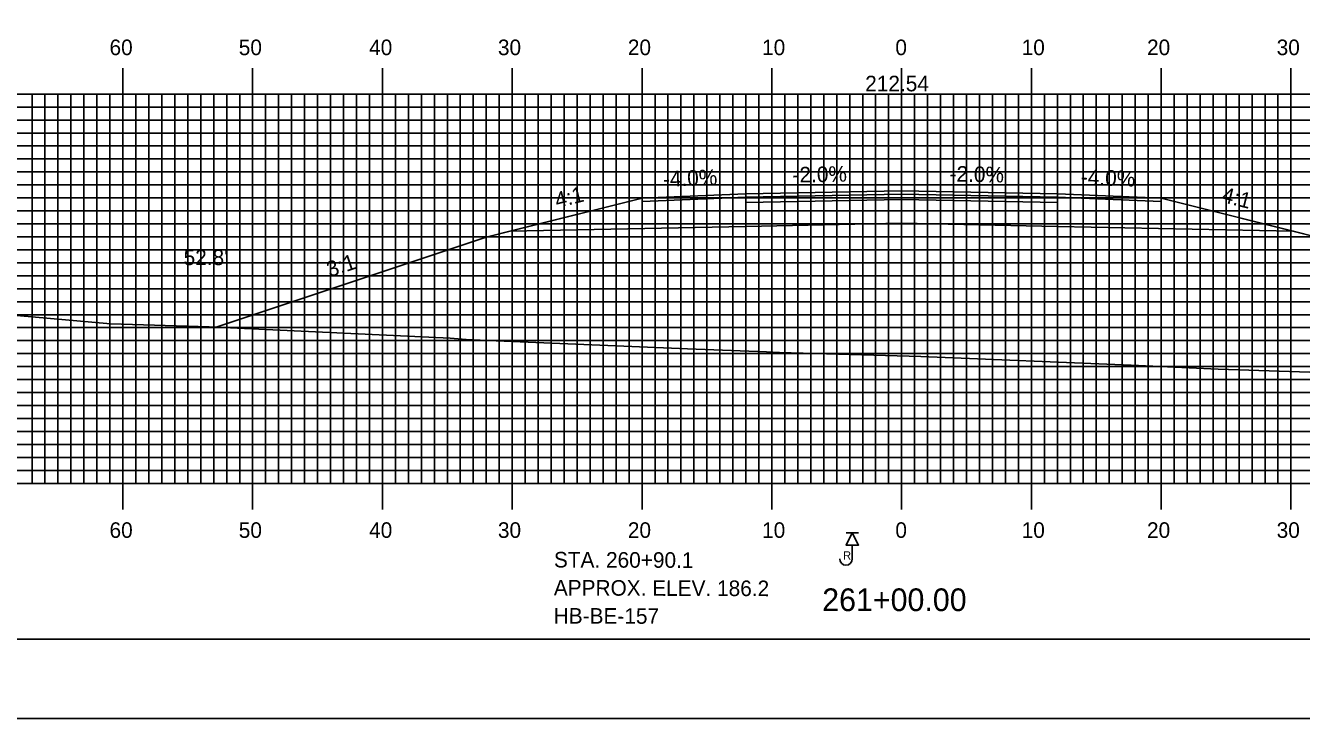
# Model space of a CAD drawing. Extents: x 1806258 to 1806601, y 442591 to 442811.
# Drawn here: x 1806356.2 to 1806454.5, y 442590.5 to 442643.9 of the extents above; entities that cross this region are included whole.
import ezdxf

# ---------------------------------------------------------------- set-up
doc = ezdxf.new("R2010")
doc.units = 0
for name, color, linetype in [('ANNOTATION', 7, 'Continuous'), ('BORDER', 7, 'Continuous'), ('BORING - REFUSAL', 7, 'Continuous'), ('D_Roadway_Centerline', 7, 'Continuous'), ('D_Roadway_Centerline_Text', 7, 'Continuous'), ('D_Roadway_Edge_Shoulder', 7, 'Continuous'), ('D_Roadway_Edge_TW', 7, 'Continuous'), ('D_Roadway_Pavement', 7, 'Continuous'), ('D_Roadway_SlopeLines', 7, 'Continuous'), ('D_Roadway_SubGrade', 7, 'Continuous'), ('D_Text_Standard', 7, 'Continuous'), ('H_V ANNOTATION', 7, 'Continuous'), ('MAJOR', 7, 'Continuous'), ('MINOR', 7, 'Continuous'), ('PLOT BOUNDARY', 7, 'Continuous'), ('S_Roadway_Centerline', 7, 'Continuous')]:
    doc.layers.add(name, color=color, linetype=linetype)

msp = doc.modelspace()

# ---------------------------------------------------------------- linework, layer by layer
at = {"layer": 'BORDER'}
msp.add_lwpolyline([(1806274.133, 442596.665), (1806594.133, 442596.665), (1806594.133, 442806.665), (1806274.133, 442806.665)], close=True, dxfattribs=at)
at = {"layer": 'BORING - REFUSAL'}
for p, q in [((1806420.412, 442604.865), (1806419.453, 442604.865)), ((1806419.933, 442603.906), (1806419.933, 442602.847))]:
    msp.add_line(p, q, dxfattribs=at)
msp.add_lwpolyline([(1806419.933, 442604.865), (1806420.412, 442603.906), (1806419.453, 442603.906)], close=True, dxfattribs=at)
msp.add_arc((1806419.448, 442602.847), 0.485, 180, 0, dxfattribs=at)
at = {"layer": 'D_Roadway_Centerline'}
msp.add_lwpolyline([(1806370.932, 442620.713), (1806391.733, 442627.646), (1806393.559, 442628.103), (1806403.733, 442630.646), (1806411.733, 442630.966), (1806423.733, 442631.206), (1806435.733, 442630.966), (1806443.733, 442630.646), (1806453.907, 442628.103), (1806455.733, 442627.646), (1806490.643, 442616.01)], dxfattribs=at)
at = {"layer": 'D_Roadway_Edge_Shoulder'}
for points in [[(1806411.733, 442630.966), (1806403.733, 442630.646), (1806403.733, 442630.396), (1806411.733, 442630.716)], [(1806435.733, 442630.966), (1806443.733, 442630.646), (1806443.733, 442630.396), (1806435.733, 442630.716)]]:
    msp.add_lwpolyline(points, close=True, dxfattribs=at)
at = {"layer": 'D_Roadway_Edge_TW'}
msp.add_lwpolyline([(1806411.733, 442630.716), (1806411.733, 442630.966), (1806423.733, 442631.206), (1806435.733, 442630.966), (1806435.733, 442630.716), (1806423.733, 442630.956)], close=True, dxfattribs=at)
at = {"layer": 'D_Roadway_Pavement'}
msp.add_lwpolyline([(1806411.733, 442630.3), (1806411.733, 442630.716), (1806423.733, 442630.956), (1806435.733, 442630.716), (1806435.733, 442630.3), (1806423.733, 442630.54)], close=True, dxfattribs=at)
at = {"layer": 'D_Roadway_SlopeLines'}
for points in [[(1806403.733, 442630.646), (1806391.733, 442627.646), (1806370.932, 442620.713)], [(1806443.733, 442630.646), (1806455.733, 442627.646), (1806490.643, 442616.01)]]:
    msp.add_lwpolyline(points, dxfattribs=at)
at = {"layer": 'D_Roadway_SubGrade'}
msp.add_lwpolyline([(1806411.733, 442628.466), (1806393.559, 442628.103), (1806403.733, 442630.646), (1806403.733, 442630.396), (1806411.733, 442630.716), (1806423.733, 442630.956), (1806435.733, 442630.716), (1806443.733, 442630.396), (1806443.733, 442630.646), (1806453.907, 442628.103), (1806435.733, 442628.466), (1806423.733, 442628.706)], close=True, dxfattribs=at)
at = {"layer": 'MAJOR'}
for p, q in [((1806363.733, 442640.669), (1806363.733, 442638.665)), ((1806373.733, 442640.669), (1806373.733, 442638.665)), ((1806383.733, 442640.669), (1806383.733, 442638.665)), ((1806393.733, 442640.669), (1806393.733, 442638.665)), ((1806403.733, 442640.669), (1806403.733, 442638.665)), ((1806413.733, 442640.669), (1806413.733, 442638.665)), ((1806423.733, 442640.669), (1806423.733, 442638.665)), ((1806433.733, 442640.669), (1806433.733, 442638.665)), ((1806443.733, 442640.669), (1806443.733, 442638.665)), ((1806453.733, 442640.669), (1806453.733, 442638.665)), ((1806283.733, 442638.665), (1806563.733, 442638.665)), ((1806283.733, 442638.665), (1806563.733, 442638.665)), ((1806363.733, 442608.665), (1806363.733, 442638.665)), ((1806373.733, 442608.665), (1806373.733, 442638.665)), ((1806383.733, 442608.665), (1806383.733, 442638.665)), ((1806393.733, 442608.665), (1806393.733, 442638.665)), ((1806403.733, 442608.665), (1806403.733, 442638.665)), ((1806413.733, 442608.665), (1806413.733, 442638.665)), ((1806423.733, 442608.665), (1806423.733, 442638.665)), ((1806433.733, 442608.665), (1806433.733, 442638.665)), ((1806443.733, 442608.665), (1806443.733, 442638.665)), ((1806453.733, 442608.665), (1806453.733, 442638.665)), ((1806283.733, 442633.665), (1806563.733, 442633.665)), ((1806283.733, 442628.665), (1806563.733, 442628.665)), ((1806283.733, 442623.665), (1806563.733, 442623.665)), ((1806283.733, 442618.665), (1806563.733, 442618.665)), ((1806283.733, 442613.665), (1806563.733, 442613.665)), ((1806283.733, 442608.665), (1806563.733, 442608.665)), ((1806283.733, 442608.665), (1806563.733, 442608.665)), ((1806363.733, 442606.661), (1806363.733, 442608.665)), ((1806373.733, 442606.661), (1806373.733, 442608.665)), ((1806383.733, 442606.661), (1806383.733, 442608.665)), ((1806393.733, 442606.661), (1806393.733, 442608.665)), ((1806403.733, 442606.661), (1806403.733, 442608.665)), ((1806413.733, 442606.661), (1806413.733, 442608.665)), ((1806423.733, 442606.661), (1806423.733, 442608.665)), ((1806433.733, 442606.661), (1806433.733, 442608.665)), ((1806443.733, 442606.661), (1806443.733, 442608.665)), ((1806453.733, 442606.661), (1806453.733, 442608.665))]:
    msp.add_line(p, q, dxfattribs=at)
at = {"layer": 'MINOR'}
for p, q in [((1806356.733, 442608.665), (1806356.733, 442638.665)), ((1806357.733, 442608.665), (1806357.733, 442638.665)), ((1806358.733, 442608.665), (1806358.733, 442638.665)), ((1806359.733, 442608.665), (1806359.733, 442638.665)), ((1806360.733, 442608.665), (1806360.733, 442638.665)), ((1806361.733, 442608.665), (1806361.733, 442638.665)), ((1806362.733, 442608.665), (1806362.733, 442638.665)), ((1806364.733, 442608.665), (1806364.733, 442638.665)), ((1806365.733, 442608.665), (1806365.733, 442638.665)), ((1806366.733, 442608.665), (1806366.733, 442638.665)), ((1806367.733, 442608.665), (1806367.733, 442638.665)), ((1806368.733, 442608.665), (1806368.733, 442638.665)), ((1806369.733, 442608.665), (1806369.733, 442638.665)), ((1806370.733, 442608.665), (1806370.733, 442638.665)), ((1806371.733, 442608.665), (1806371.733, 442638.665)), ((1806372.733, 442608.665), (1806372.733, 442638.665)), ((1806374.733, 442608.665), (1806374.733, 442638.665)), ((1806375.733, 442608.665), (1806375.733, 442638.665)), ((1806376.733, 442608.665), (1806376.733, 442638.665)), ((1806377.733, 442608.665), (1806377.733, 442638.665)), ((1806378.733, 442608.665), (1806378.733, 442638.665)), ((1806379.733, 442608.665), (1806379.733, 442638.665)), ((1806380.733, 442608.665), (1806380.733, 442638.665)), ((1806381.733, 442608.665), (1806381.733, 442638.665)), ((1806382.733, 442608.665), (1806382.733, 442638.665)), ((1806384.733, 442608.665), (1806384.733, 442638.665)), ((1806385.733, 442608.665), (1806385.733, 442638.665)), ((1806386.733, 442608.665), (1806386.733, 442638.665)), ((1806387.733, 442608.665), (1806387.733, 442638.665)), ((1806388.733, 442608.665), (1806388.733, 442638.665)), ((1806389.733, 442608.665), (1806389.733, 442638.665)), ((1806390.733, 442608.665), (1806390.733, 442638.665)), ((1806391.733, 442608.665), (1806391.733, 442638.665)), ((1806392.733, 442608.665), (1806392.733, 442638.665)), ((1806394.733, 442608.665), (1806394.733, 442638.665)), ((1806395.733, 442608.665), (1806395.733, 442638.665)), ((1806396.733, 442608.665), (1806396.733, 442638.665)), ((1806397.733, 442608.665), (1806397.733, 442638.665)), ((1806398.733, 442608.665), (1806398.733, 442638.665)), ((1806399.733, 442608.665), (1806399.733, 442638.665)), ((1806400.733, 442608.665), (1806400.733, 442638.665)), ((1806401.733, 442608.665), (1806401.733, 442638.665)), ((1806402.733, 442608.665), (1806402.733, 442638.665)), ((1806404.733, 442608.665), (1806404.733, 442638.665)), ((1806405.733, 442608.665), (1806405.733, 442638.665)), ((1806406.733, 442608.665), (1806406.733, 442638.665)), ((1806407.733, 442608.665), (1806407.733, 442638.665)), ((1806408.733, 442608.665), (1806408.733, 442638.665)), ((1806409.733, 442608.665), (1806409.733, 442638.665)), ((1806410.733, 442608.665), (1806410.733, 442638.665)), ((1806411.733, 442608.665), (1806411.733, 442638.665)), ((1806412.733, 442608.665), (1806412.733, 442638.665)), ((1806414.733, 442608.665), (1806414.733, 442638.665)), ((1806415.733, 442608.665), (1806415.733, 442638.665)), ((1806416.733, 442608.665), (1806416.733, 442638.665)), ((1806417.733, 442608.665), (1806417.733, 442638.665)), ((1806418.733, 442608.665), (1806418.733, 442638.665)), ((1806419.733, 442608.665), (1806419.733, 442638.665)), ((1806420.733, 442608.665), (1806420.733, 442638.665)), ((1806421.733, 442608.665), (1806421.733, 442638.665)), ((1806422.733, 442608.665), (1806422.733, 442638.665)), ((1806424.733, 442608.665), (1806424.733, 442638.665)), ((1806425.733, 442608.665), (1806425.733, 442638.665)), ((1806426.733, 442608.665), (1806426.733, 442638.665)), ((1806427.733, 442608.665), (1806427.733, 442638.665)), ((1806428.733, 442608.665), (1806428.733, 442638.665)), ((1806429.733, 442608.665), (1806429.733, 442638.665)), ((1806430.733, 442608.665), (1806430.733, 442638.665)), ((1806431.733, 442608.665), (1806431.733, 442638.665)), ((1806432.733, 442608.665), (1806432.733, 442638.665)), ((1806434.733, 442608.665), (1806434.733, 442638.665)), ((1806435.733, 442608.665), (1806435.733, 442638.665)), ((1806436.733, 442608.665), (1806436.733, 442638.665)), ((1806437.733, 442608.665), (1806437.733, 442638.665)), ((1806438.733, 442608.665), (1806438.733, 442638.665)), ((1806439.733, 442608.665), (1806439.733, 442638.665)), ((1806440.733, 442608.665), (1806440.733, 442638.665)), ((1806441.733, 442608.665), (1806441.733, 442638.665)), ((1806442.733, 442608.665), (1806442.733, 442638.665)), ((1806444.733, 442608.665), (1806444.733, 442638.665)), ((1806445.733, 442608.665), (1806445.733, 442638.665)), ((1806446.733, 442608.665), (1806446.733, 442638.665)), ((1806447.733, 442608.665), (1806447.733, 442638.665)), ((1806448.733, 442608.665), (1806448.733, 442638.665)), ((1806449.733, 442608.665), (1806449.733, 442638.665)), ((1806450.733, 442608.665), (1806450.733, 442638.665)), ((1806451.733, 442608.665), (1806451.733, 442638.665)), ((1806452.733, 442608.665), (1806452.733, 442638.665)), ((1806283.733, 442637.665), (1806563.733, 442637.665)), ((1806283.733, 442636.665), (1806563.733, 442636.665)), ((1806283.733, 442635.665), (1806563.733, 442635.665)), ((1806283.733, 442634.665), (1806563.733, 442634.665)), ((1806283.733, 442632.665), (1806563.733, 442632.665)), ((1806283.733, 442631.665), (1806563.733, 442631.665)), ((1806283.733, 442630.665), (1806563.733, 442630.665)), ((1806283.733, 442629.665), (1806563.733, 442629.665)), ((1806283.733, 442627.665), (1806563.733, 442627.665)), ((1806283.733, 442626.665), (1806563.733, 442626.665)), ((1806283.733, 442625.665), (1806563.733, 442625.665)), ((1806283.733, 442624.665), (1806563.733, 442624.665)), ((1806283.733, 442622.665), (1806563.733, 442622.665)), ((1806283.733, 442621.665), (1806563.733, 442621.665)), ((1806283.733, 442620.665), (1806563.733, 442620.665)), ((1806283.733, 442619.665), (1806563.733, 442619.665)), ((1806283.733, 442617.665), (1806563.733, 442617.665)), ((1806283.733, 442616.665), (1806563.733, 442616.665)), ((1806283.733, 442615.665), (1806563.733, 442615.665)), ((1806283.733, 442614.665), (1806563.733, 442614.665)), ((1806283.733, 442612.665), (1806563.733, 442612.665)), ((1806283.733, 442611.665), (1806563.733, 442611.665)), ((1806283.733, 442610.665), (1806563.733, 442610.665)), ((1806283.733, 442609.665), (1806563.733, 442609.665))]:
    msp.add_line(p, q, dxfattribs=at)
at = {"layer": 'PLOT BOUNDARY'}
msp.add_lwpolyline([(1806257.946, 442590.547), (1806597.946, 442590.547), (1806597.946, 442810.547), (1806257.946, 442810.547)], close=True, dxfattribs=at)
at = {"layer": 'S_Roadway_Centerline'}
msp.add_lwpolyline([(1806283.733, 442625.827), (1806284.232, 442625.799), (1806285.695, 442625.656), (1806297.342, 442625.071), (1806307.596, 442624.499), (1806311.816, 442624.288), (1806327.979, 442622.999), (1806332.351, 442622.714), (1806337.766, 442622.677), (1806348.309, 442622.255), (1806362.78, 442620.972), (1806370.38, 442620.739), (1806388.95, 442619.857), (1806390.184, 442619.749), (1806391.268, 442619.709), (1806407.24, 442619.04), (1806413.325, 442618.794), (1806414.324, 442618.744), (1806425.22, 442618.432), (1806441.412, 442617.782), (1806448.113, 442617.46), (1806463.026, 442616.971)], dxfattribs=at)

# ---------------------------------------------------------------- texts
at = {"layer": 'ANNOTATION'}
for s, rotation, p in [('-2.0%', 1.14576, (1806415.339, 442631.839)), ('-2.0%', 358.85424, (1806427.419, 442631.933)), ('-4.0%', 2.29061, (1806405.364, 442631.513)), ('-4.0%', 357.70939, (1806437.524, 442631.696)), ('4:1', 14.03624, (1806397.181, 442629.87)), ('4:1', 345.96376, (1806448.325, 442630.36)), ('3:1', 18.43478, (1806379.671, 442624.534))]:
    msp.add_text(s, height=1.2, rotation=rotation, dxfattribs=at).set_placement(p)
at = {"layer": 'BORING - REFUSAL'}
msp.add_text('R', height=0.64, dxfattribs=at).set_placement((1806419.224, 442602.791))
for s, p in [('STA. 260+90.1', (1806396.943, 442602.186)), ('APPROX. ELEV. 186.2', (1806396.936, 442600.026)), ('HB-BE-157', (1806396.929, 442597.866))]:
    msp.add_text(s, height=1.2, rotation=359.81416, dxfattribs=at).set_placement(p)
at = {"layer": 'D_Roadway_Centerline'}
for s, p in [('C', (1806423.727, 442631.206)), ('L', (1806423.733, 442631.199))]:
    msp.add_text(s, height=0.0146, dxfattribs=at).set_placement(p)
at = {"layer": 'D_Roadway_Centerline_Text'}
msp.add_text('212.54', height=1.2, dxfattribs=at).set_placement((1806420.928, 442638.877))
at = {"layer": 'D_Text_Standard'}
msp.add_text("52.8'", height=1.2, dxfattribs=at).set_placement((1806368.412, 442625.482))
at = {"layer": 'H_V ANNOTATION'}
for s, height, p in [('60', 1.2, (1806362.705, 442641.665)), ('50', 1.2, (1806372.662, 442641.665)), ('40', 1.2, (1806382.705, 442641.665)), ('30', 1.2, (1806392.63, 442641.665)), ('20', 1.2, (1806402.641, 442641.665)), ('10', 1.2, (1806412.983, 442641.665)), ('0', 1.2, (1806423.251, 442641.665)), ('10', 1.2, (1806432.983, 442641.665)), ('20', 1.2, (1806442.641, 442641.665)), ('30', 1.2, (1806452.63, 442641.665)), ('60', 1.2, (1806362.705, 442604.465)), ('50', 1.2, (1806372.662, 442604.465)), ('40', 1.2, (1806382.705, 442604.465)), ('30', 1.2, (1806392.63, 442604.465)), ('20', 1.2, (1806402.641, 442604.465)), ('10', 1.2, (1806412.983, 442604.465)), ('0', 1.2, (1806423.251, 442604.465)), ('10', 1.2, (1806432.983, 442604.465)), ('20', 1.2, (1806442.641, 442604.465)), ('30', 1.2, (1806452.63, 442604.465)), ('261+00.00', 1.75, (1806417.615, 442598.821))]:
    msp.add_text(s, height=height, dxfattribs=at).set_placement(p)

doc.saveas('drawing.dxf')
